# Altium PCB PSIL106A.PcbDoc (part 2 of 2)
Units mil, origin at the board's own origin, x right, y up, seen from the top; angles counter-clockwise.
Board outline 4000 x 3327 mil, 2 copper layers (Top Layer, Bottom Layer), stack 62 mil thick; 63 components, 23 nets, 108 pads, 247 vias.
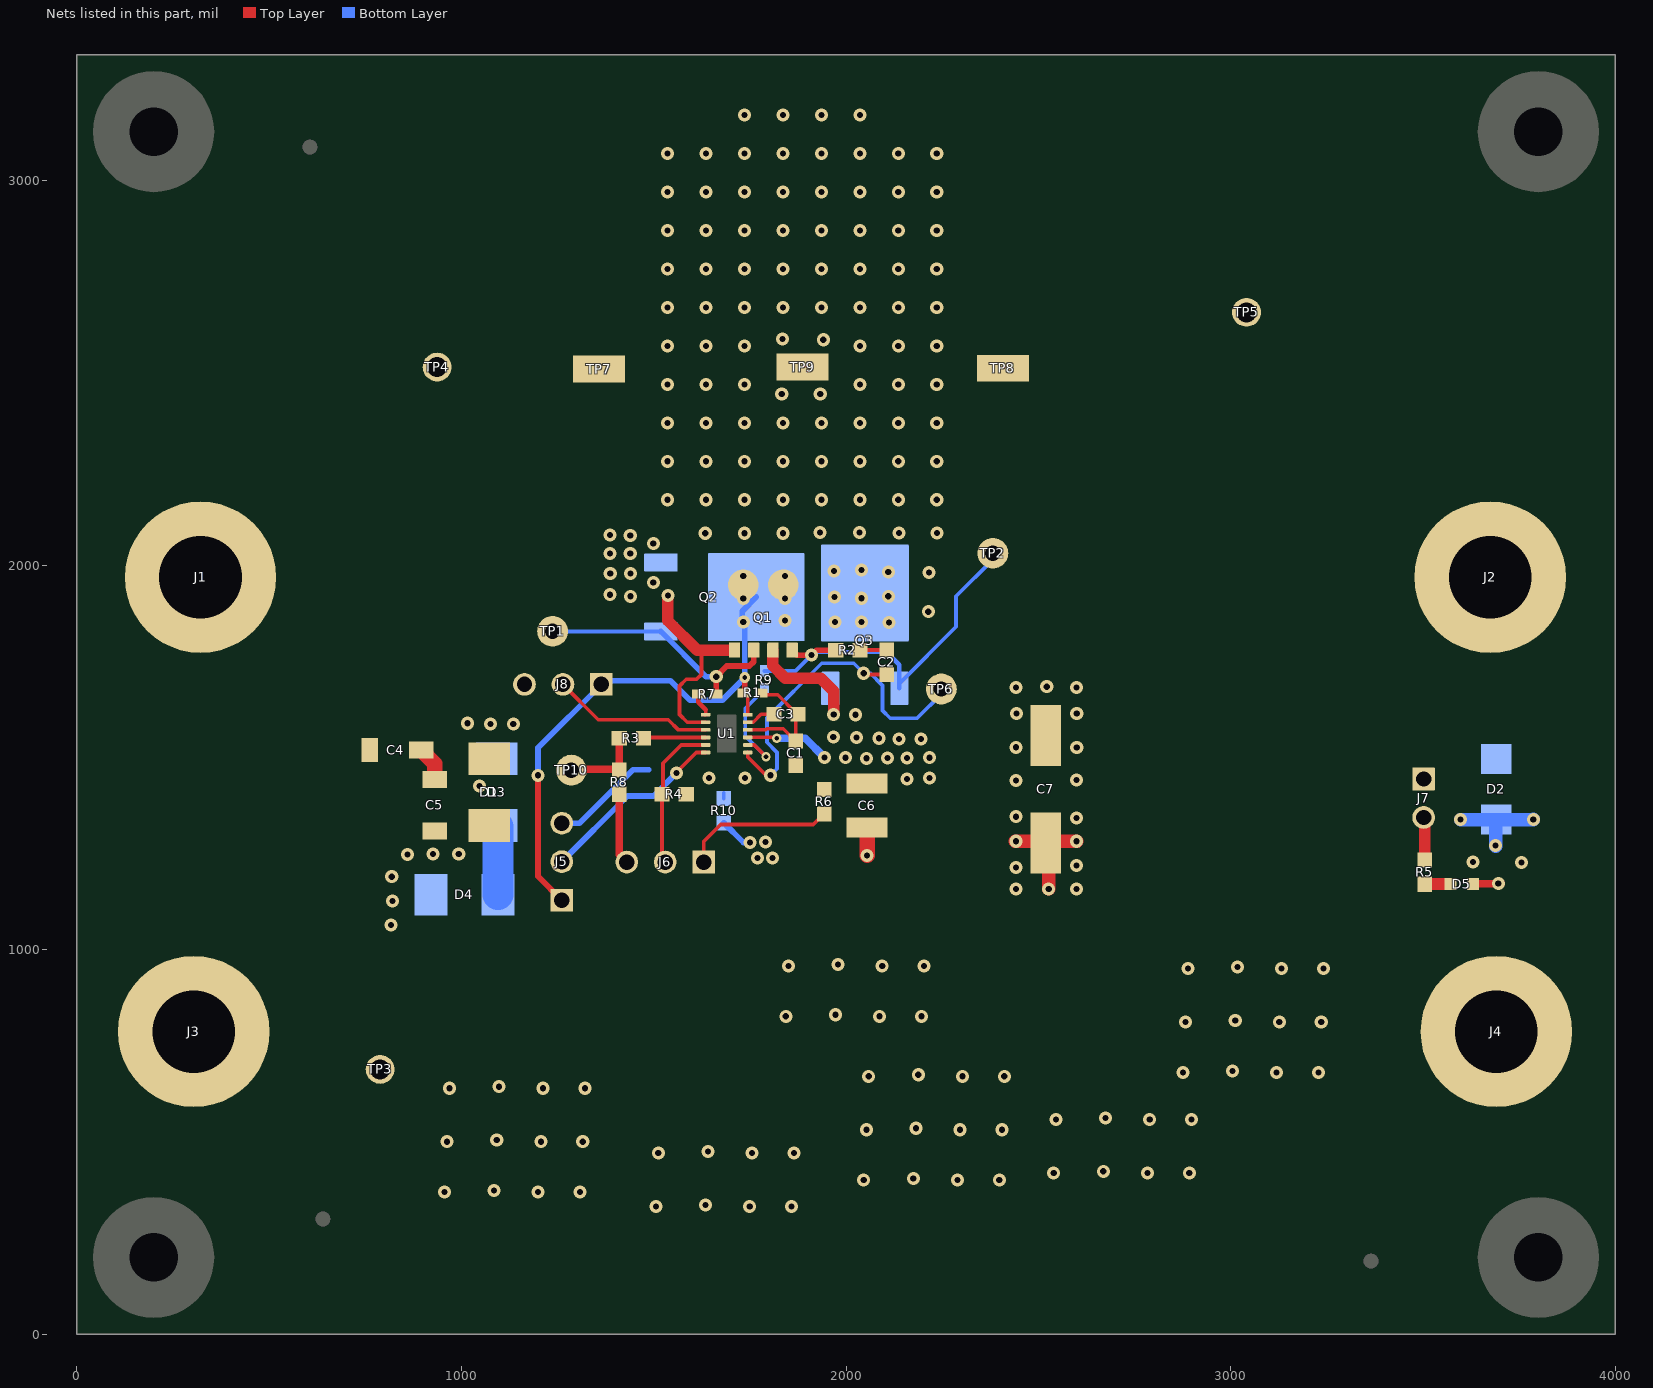
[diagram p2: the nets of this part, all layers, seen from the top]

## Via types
v1: diameter 34, hole 16, Top Layer to Bottom Layer, 241 vias
v2: diameter 19.68, hole 7.87, Top Layer to Bottom Layer, 3 vias
v3: diameter 24, hole 12, Top Layer to Bottom Layer, 2 vias
v4: diameter 28, hole 12, Top Layer to Bottom Layer, 1 vias

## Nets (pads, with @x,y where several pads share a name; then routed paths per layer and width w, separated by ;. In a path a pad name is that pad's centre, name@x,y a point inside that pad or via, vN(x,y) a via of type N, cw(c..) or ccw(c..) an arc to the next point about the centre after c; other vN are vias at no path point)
AGND: C1.2 C2.2 J5.3 R4.1 R10.2 TP6.1 U1.7 | length 1266.5
  Top Layer w10: U1.7@1744.49,1512.8 1744.49,1501.03 1791.77,1453.75 v1(1804,1453.75) ; v1(2046,1719) 2048.88,1716.12 C2.2@2106,1716.12
  Bottom Layer w10: R10.2@1682,1393.28 R10.2@1682,1408.17 ; v1(1804,1453.75) 1821,1470.75 1821,1513.33 1794.61,1539.72 1794.61,1602.76 1936.85,1745 2020,1745 v1(2046,1719) 2063.46,1719 2095,1687.46 2095,1621.9 2114.9,1602 2185,1602 2248,1665 TP6.1@2248,1678
  Bottom Layer w15: J5.3@1261,1329 1307,1329 1446,1468 1487,1468
  other v1: 1644,1446.17 1737,1447
NetC1_1: C1.1 C3.2 R1.1 U1.10 | length 312.7
  Top Layer w9.6: U1.10@1744.49,1571.85 1791,1571.85 1793.95,1574.8 1836.7,1574.8 C1.1@1869,1542.5 1869,1605.5 C3.2@1874.5,1611 ; R1.1@1794.62,1663 1822.5,1663 1868.99,1616.5 C3.2@1874.5,1611 ; C3.2@1875.5,1612 C3.2@1874.5,1611
NetC2_1: C2.1 R2.1 | length 69.6
  Top Layer w10: R2.1@2036.5,1778.96 2105.85,1778.96 C2.1@2106,1779.12
NetC3_1: C3.1 U1.11 | length 79.3
  Top Layer w9.5: U1.11@1744.49,1591.54 1758.81,1591.54 1779.27,1612 C3.1@1812.5,1612 ; C3.1@1815.5,1605 C3.1@1817.5,1607
NetC4_1: C4.1 D1.2 D3.1 J1.1 J8.3 Q1.1 Q2.3 TP7.1 U1.2 | length 557.9
  Top Layer w9.7: 1613.04,1778.96 1624,1768 1624,1716 1611.63,1703.63 1584.63,1703.63 1567,1686 1567,1612 1587.46,1591.54 U1.2@1635.04,1591.54
  Top Layer w30: v1(1537,1921) 1537,1855 1613.04,1778.96 Q1.1@1710,1778.96
  other v1: 1047.31,1426 1076,1587 1135,1587 1016,1589 1439.25,1919 1386,1923.24 1499,1955 1387,1978 1439.25,1978 1386,2030 1439,2030 1499,2056 1439,2077 1386,2078
NetC4_2: C4.2 C5.1 | length 90.9
  Top Layer w40: C4.2@895.63,1519.29 930.64,1484.28 C5.1@930.64,1442.86
NetC6_1: C6.1 C7.1 D2.1 J2.1 J7.1 Q1.3 Q3.3 R6.2 TP8.1 U1.9 | length 507.9
  Top Layer w9.6: U1.9@1744.65,1552 U1.9@1744.49,1552.17 1817.83,1552.17 v3(1820,1550)
  Top Layer w30: Q1.3@1810,1778.96 1810,1738 1842,1706 1934.36,1706 1968,1672.36 v1(1968,1612)
  Bottom Layer w20: v3(1820,1550) 1894.06,1550 v1(1944.06,1500)
  other v1: 2442,1440 2599,1441 2159,1444 2217,1446.46 2053,1497.79 2108,1498.3 1999,1499.37 2159,1498.76 2217,1499.37 2442,1526.4 2600,1526 2138,1548 2195,1548 2086,1550 2027,1552 1967,1553 2025,1611 2443.34,1614 2600,1614 2442,1682 2599.66,1682.31 2522,1684
NetD3_2: D3.2 D4.2 | length 184.5
  Bottom Layer w20: D4.2@1092.51,1145.49 D4.2@1095.01,1143
  Bottom Layer w30: D3.2@1092.51,1322.98 D3.2@1095.01,1320.49
  Bottom Layer w80: D4.2@1095.01,1143 D3.2@1095.01,1320.49
NetD5_1: D5.1 R5.1 | length 66.7
  Top Layer w30: R5.1@3505,1170.5 3505.5,1171 D5.1@3571.47,1171
NetJ5_1: J5.1 J8.1 Q1.5-6 Q1.7-8 Q2.4 Q3.4 R1.2 TP9.1 U1.12 | length 1402.1
  Top Layer w10: R1.2@1737,1674 1744.49,1666.51 U1.12@1744.49,1611.22
  Top Layer w15: v1(1199,1453.6) 1199,1191 J5.1@1261,1129 ; R1.2@1737,1674 v4(1737,1708)
  Bottom Layer w15: v1(1199,1453.6) 1199,1525 J8.1@1364,1690 1373.18,1699.18 1543.39,1699.18 1594.09,1648.47 1678.47,1648.47 1737,1707 v4(1737,1708) Q2.4@1737,1845 ; Q2.4@1730,1845 1730,1880.32 Q2.4@1766.68,1917
  other v1: 2112,1851 1733,1852 1971,1852 2040,1852 1841,1856 2214,1879 1733,1913 1841,1913 2040,1914 1970,1917 2110,1919 1733,1972 1841,1972 2216,1981 2110,1982 1969,1985 2040,1987 1634,2083 1736,2083 1836,2083 2138,2083.45 2237,2083.45 1932,2085 2035,2085 1536,2170 1636,2170 1736,2170 1836,2170 1936,2170 2036,2170 2136,2170 2236,2170 1536,2270 1636,2270 1736,2270 1836,2270 1936,2270 2036,2270 2136,2270 2236,2270 1536,2370 1636,2370 1736,2370 1836,2370 1936,2370 2036,2370 2136,2370 2236,2370 1833,2445 1933,2445 1536,2470 1636,2470 1736,2470 2036,2470 2136,2470 2236,2470 1536,2570 1636,2570 1736,2570 2036,2570 2136,2570 2236,2570 1941,2586 1835,2588 1536,2670 1636,2670 1736,2670 1836,2670 1936,2670 2036,2670 2136,2670 2236,2670 1536,2770 1636,2770 1736,2770 1836,2770 1936,2770 2036,2770 2136,2770 2236,2770 1536,2870 1636,2870 1736,2870 1836,2870 1936,2870 2036,2870 2136,2870 2236,2870 1536,2970 1636,2970 1736,2970 1836,2970 1936,2970 2036,2970 2136,2970 2236,2970 1536,3070 1636,3070 1736,3070 1836,3070 1936,3070 2036,3070 2136,3070 2236,3070 1736,3170 1836,3170 1936,3170 2036,3170
NetJ5_2: J5.2 U1.6 | length 490.9
  Top Layer w9.8: v1@1559.66,1461.66 1610.8,1512.8 U1.6@1635.04,1512.8
  Bottom Layer w15: J5.2@1261,1229 1432,1400 1499.66,1400 v1(1559.66,1460)
NetJ6_1: J6.1 R6.1 | length 396.1
  Top Layer w10: J6.1@1630,1228 1630,1281.08 1674.3,1325.38 1914.93,1325.38 R6.1@1943,1353.44
NetJ6_2: J6.2 R4.2 U1.5 | length 392.3
  Top Layer w9.8: J6.2@1530,1228 1521.5,1236.5 R4.2@1521.5,1404 1524,1406.5 1524,1485 1571.48,1532.48 U1.5@1635.04,1532.48
NetJ6_3: J6.3 R8.2 | length 184.3
  Top Layer w20: R8.2@1410.5,1404.18 1410.5,1247.5 J6.3@1430,1228
NetJ7_2: J7.2 R5.2 | length 111.7
  Top Layer w30: J7.2@3502,1344 3505,1341 R5.2@3505,1233.5
NetJ8_2: J8.2 U1.3 | length 420
  Top Layer w9.8: 1564.15,1571.85 U1.3@1635.04,1571.85
  Top Layer w10: J8.2@1264,1690 1356,1598 1538,1598 1564.15,1571.85
NetQ1_2: Q1.2 Q2.1 R7.2 TP1.1 | length 668
  Top Layer w15: R7.2@1662.62,1665 v1(1662.62,1710) 1690.12,1737.5 1748.5,1737.5 1760,1749 Q1.2@1760,1778.96
  Bottom Layer w10: TP1.1@1238,1812 1253.24,1827.24 Q2.1@1518.65,1827.24
  Bottom Layer w15: Q2.1@1518.65,1827.24 1635.88,1710 v1(1662.62,1710)
NetQ1_4: Q1.4 Q3.1 R2.2 R9.2 TP2.1 | length 1009.6
  Top Layer w15: Q1.4@1860,1778.96 1872.96,1766 v1(1910,1766) 1922.96,1778.96 R2.2@1973.5,1778.96
  Bottom Layer w10: R9.2@1787.99,1724.62 1868.62,1724.62 v1(1910,1766) 1918,1774 2105.9,1774 2106.9,1773 ; Q3.1@2138.76,1692.76 2286,1840 2286,1919 2382,2015 TP2.1@2382,2031
  Bottom Layer w12: 2106.9,1773 2138.76,1741.14 2138.76,1692.76 Q3.1@2138.76,1679.65
NetR3_1: R3.1 R8.1 TP10.1 | length 176.3
  Top Layer w20: TP10.1@1302.53,1469 1408.68,1469 R8.1@1410.5,1467.17 R3.1@1410.5,1534.71
NetR3_2: R3.2 U1.4 | length 144.1
  Top Layer w9.8: R3.2@1490.95,1552.17 U1.4@1635.04,1552.17
NetR7_1: R7.1 U1.1 | length 65.2
  Top Layer w9: U1.1@1635.04,1611.22 1635.04,1623.96
  Top Layer w10: U1.1@1631.81,1611.22 U1.1@1635.04,1611.22
  Top Layer w12: R7.1@1615.38,1665 1615.38,1643.62 1635.04,1623.96
NetR9_1: R9.1 U1.8 | length 278.6
  Top Layer w9.7: U1.8@1744.49,1532.48 1761.52,1532.48 v3(1792,1502)
  Bottom Layer w9.7: R9.1@1787.99,1677.38 1738,1627.39 1738,1556 v3(1792,1502)
SGND: C5.2 C6.2 C7.2 D1.1 D2.2 D4.1 D5.2 J3.1 J4.1 R10.1 TP3.1 TP4.1 TP5.1 | length 795
  Top Layer w20: D1.1@1090,1320.46 D1.1@1092.52,1322.98 ; D5.2@3630.53,1171 3631.53,1172 v1(3696,1172) 3703,1172 v1@3702,1171
  Top Layer w30: D1.1@1092.52,1322.98 1095.61,1319.89 D1.1@1096.21,1319.89
  Top Layer w35: v1@2439.71,1282.23 v1(2442,1282.23) 2515.01,1282.23 C7.2@2519.68,1277.56 ; v1(2527,1158) 2527,1267.24 2524,1270.24 2525.5,1271.74 C7.2@2519.68,1277.56 ; v1(2599.66,1282.23) 2524.36,1282.23 C7.2@2519.68,1277.56
  Top Layer w40: v1(2055,1245) C6.2@2055,1317.91
  Bottom Layer w15: R10.1@1682,1330.28 1733.28,1279 v1(1750.28,1279)
  Bottom Layer w35: v1(3598.06,1338.58) D2.2@3690.94,1338.58 ; v1@3689,1269 v1(3689,1270.88) 3689,1330.53 3694,1335.53 D2.2@3690.94,1338.58 ; v1(3787,1339) 3786.58,1338.58 D2.2@3690.94,1338.58
  other v1: 1506,332.38 1749.62,332.38 1858.62,332.38 1635,336.38 956,370 1199.62,370 1308.62,370 1085,374 2046,401 2289.62,401 2398.62,401 2175,405 2540,420 2783.62,420 2892.62,420 2669,424 1512,471.38 1755.62,471.38 1864.62,471.38 1641,475.38 963,501 1206.62,501 1315.62,501 1092,505 2053,532 2296.62,532 2405.62,532 2182,536 2546,559 2789.62,559 2898.62,559 2675,563 969,640 1212.62,640 1321.62,640 1098,644 2059,671 2302.62,671 2411.62,671 2188,675 2876,681 3119.62,681 3228.62,681 3005,685 2883,812 3126.62,812 3235.62,812 3012,816 1843.5,827 2087.13,827 2196.13,827 1972.5,831 2889,951 3132.62,951 3241.62,951 3018,955 1850.5,958 2094.13,958 2203.13,958 1979.5,962 817,1064.5 820.46,1126.97 2442,1158 2599.66,1158 818.89,1190 2442,1214.23 2599.66,1218.73 3756.04,1227 3630.53,1228 1770,1238.36 1809,1239 860,1248 926,1249 993.24,1249 1791,1280 2599.66,1343 2442,1346
pads on no net: FID1.1 FID2.1 FID3.1 FID4.1 FID5.1 FID6.1 H1.1 H2.1 H3.1 H4.1 H5.0 H6.0 H7.0 H8.0 U1.13
copper on no net:
  other v2: 1689.76,1522.64 1690.76,1562.01 1689.76,1601.38

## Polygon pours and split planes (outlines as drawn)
NetC4_1 on Top Layer "TOP_LAYER_NETC4_1_P023" (solid, remove dead copper, pour order 23): 1603.25,2008.95 1616,1996.2 1616,1834.51 1649.51,1801 1726,1801 1732.6,1794.4 1732.6,1759.6 1702,1729 1571.51,1729 1541,1698.49 1541,1638 1426.26,1638 1294.52,1638 1189,1532.48 1189.7,1531.78 1190,1466.17 1190,1400 101.02,1400 39.37,1461.67 39.37,2116.14 39.37,2999.37 293,3253 1446.41,3253 1461.41,3238 1461.41,2150.79
SGND on Top Layer "TOP_LAYER_SGND_P021" (solid, remove dead copper, pour order 21): 3949,1369 3982,1336 3982,37 2167,37 262,37 38,261 38,1369
AGND on Top Layer "TOP_LAYER_AGND_P007" (solid, remove dead copper, pour order 7): 1575,1514.32 1855,1514.32 1888,1514.32 1888,1373.02 1679.03,1373.02 1575,1373.02
NetJ5_1 on Top Layer "TOP_LAYER_NETJ5_1_P009" (solid, remove dead copper, pour order 9): 1602.99,2044.57 1644,2003.56 1644,1859.92 1675.75,1828.17 1899.83,1828.17 2263,1828.17 2263,3254 2260,3257 1510,3257 1501,3248 1501,2146 1592.5,2054.5 1602.43,2044.57
NetC6_1 on Top Layer "TOP_LAYER_NETC6_1_P010" (solid, remove dead copper, pour order 10): 1918.34,1405.66 1913,1411 1913,1526 1932,1545 1932,1642 1882,1692 1833,1692 1792.87,1732.13 1792.87,1798 1878,1798 2081.99,1594.01 2312.01,1594.01 2312.01,3225.01 2345,3258 3765,3258 3954,3069 3954,1448 3912.04,1406.04 2841,1406 2841.5,1405.66
SGND on Bottom Layer "BOTTOM_LAYER_SGND_P017" (solid, remove dead copper, pour order 17): 31,3291 3962,3291 3962,40 31,40
NetJ5_1 on Bottom Layer "BOTTOM_LAYER_NETJ5_1_P011" (solid, remove dead copper, pour order 11): 1635.04,2013 1500,2148.04 1500,3262 1521,3283 2233,3283 2262,3254 2262,1838 2226,1802 1635.04,1802
NetC6_1 on Bottom Layer "BOTTOM_LAYER_NETC6_1_P008" (solid, remove dead copper, pour order 8): 1848.73,1730.75 2677,1730.75 2677,1389 1848.73,1389
AGND on Bottom Layer "BOTTOM_LAYER_AGND_P003" (solid, remove dead copper, pour order 3): 1794.25,1592.25 1831.4,1555.09 1833,1504 1833,1390 1832.51,1389.51 1832.51,1373 1713.46,1373 1679.05,1373 1677.09,1374.96 1460,1374.96 1460,1592.25
NetC6_1 on Bottom Layer "BOTTOM_LAYER_NETC6_1_P014" (solid, remove dead copper, pour order 14): 3619,1480 3646,1453 3741,1453 3764,1476 3764,1747 3886,1869 3886,2054.96 3763.96,2177 3583,2177 3467,2061 3467,1886 3619,1734
NetC4_1 on Bottom Layer "BOTTOM_LAYER_NETC4_1_P002" (solid, remove dead copper, pour order 2): 1549,1886 1310,1886 1277,1919 1277,2127 1301,2151 1461.2,2151 1561,2051.2 1561,1898
NetC4_1 on Bottom Layer "BOTTOM_LAYER_NETC4_1_P025" (solid, remove dead copper, pour order 25): 966,1625 966,1404 1181.1,1404 1181.1,1624.9 1181,1625

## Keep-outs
Keep-Out Layer:
  text ".Layer_Name" at 577,-858.49 h60

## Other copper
Top Layer:
  pour cut-out: 1411,1646.61 1411,1731.89 1402.89,1740 1236.61,1740 1228,1731.39 1228,1680 1262,1646 1262,1584 1372,1584 1411,1623
  pour cut-out: 1680,1272 1680,1189.61 1668.39,1178 1404,1178 1385.29,1196.71 1385.29,1244 1403.29,1262 1651.76,1262 1661.76,1272
  pour cut-out: 1375.2,1359.5 1311,1359.5 1311,1383 1371.2,1383 1375.2,1383
  pour cut-out: 1307,1081 1311,1085 1311,1369 1305.94,1369 1305.94,1098.94 1298,1091 1226,1091 1223,1094 1223,1136 1221,1138 1216.76,1138 1215.76,1137 1215.76,1084.24 1219,1081
  text ".Layer_Name" at 577,-858.49 h60
Bottom Layer:
  pour cut-out: 3593.51,1546 3593.51,1452.49 3620,1426 3760,1426 3789.49,1455.49 3789.49,1540 3778,1540 3778,1513 3777,1512 3777,1462 3750,1435 3630,1435 3604,1461 3604,1546
  pour cut-out: 3462.18,1490 3537.71,1490 3550,1477.71 3550,1323 3521,1294 3482,1294 3452,1324 3452,1479.82
  text ".Layer_Name" at 577,-858.49 h60

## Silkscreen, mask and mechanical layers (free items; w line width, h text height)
Top Overlay:
  lines w6: 1568,1963 1568,2034
  text "'.PRJ_Number'.PCB_Rev" at 2397,2832 h150
  text "LM74800EVM-CD" at 327,2822 h150
  text "VOUT" at 2340,2640 h35
  text "GND4" at 3123,2638 h35
  text "GND3" at 882,2634 h35
  text "VIN" at 1309,2634 h35
  text "VOUT_ALWAYS_ON" at 1752.36,2599 h35
  text "VOUT+" at 3532,2278 h60
  text "HGATE" at 2457,2007.7 h35
  text "DGATE" at 984.25,1807.5 h35
  text "GND2" at 2203.13,1782.58 h30
  text "VIN+" at 224,1666 h60
  text "VIN_MON" at 1162.51,1569.58 h30
  text "VIN-" at 208,1038 h60
  text "GND1" at 728.77,802 h35
  text "VOUT-" at 3568,480 h60
  text ".Layer_Name" at 577,-858.49 h60
Bottom Overlay:
  circle w10: c2138.9,1603.76 r15
  circle w10: c1513.54,1767 r15
  text ".Layer_Name" at 577,-858.49 h60
Top Paste:
  text ".Layer_Name" at 577,-858.49 h60
Bottom Paste:
  text ".Layer_Name" at 577,-858.49 h60
Top Solder:
  text ".Layer_Name" at 577,-858.49 h60
  text ".Layer_Name" at 577,-858.49 h60
Bottom Solder:
  text ".Layer_Name" at 577,-858.49 h60
Drill Guide:
  text ".Layer_Name" at 577,-858.49 h60
M1 Board Outline:
  the board outline again, w10
  text ".Layer_Name" at 962.71,-858.49 h60
M2 Board Dimensions:
  rectangle: 0,-275 125,-150
  rectangle: 125,-400 500,-275
  lines w7: 0,-275 1000,-275 ; 125,-400 125,-150 ; 250,-400 250,-150 ; 500,-400 500,-150 ; 750,-400 750,-150 ; 0,-400 1000,-400 1000,-150 0,-150 0,-400
M3 3D STEP Top:
  text ".Layer_Name" at 577,-858.49 h60
M4 3D STEP Bottom:
  text ".Layer_Name" at 577,-858.49 h60
M5 Assembly Top:
  lines w10: -292,-930.17 6308,-930.17 ; -292,-726.83 6310,-726.83 ; -292,-523.5 -292,-1133.5 3713,-1133.5 6310,-1133.5 6310,-523.5 -291.5,-523.5 -291.5,-1133.5 1284,-1133.5 ; 2173,-1133.5 2173,-523.5 ; 3440,-726.83 3440,-523.5 ; 4280,-726.83 4280,-523.5 ; 4902,-1140 4902,-937.17
  text "COMPONENTS MARKED 'DNP' SHOULD NOT BE POPULATED." at 1153.5,-318.5 h60
  text "ASSEMBLY VARIANT:" at 1153,-434 h60
  text ".VariantName" at 2189,-434 h60
  text "PCB VIEWED FROM TOP SIDE" at -228.5,-655.67 h60
  text "BOARD #:" at 2248,-655.67 h60
  text ".PRJ_Number" at 2793.5,-655.67 h60
  text "REV:" at 3638,-655.67 h60
  text ".PCB_Rev" at 3929.5,-655.67 h60
  text "SVN REV:" at 4476,-655.67 h60
  text ".VersionControl_RevNumber" at 4982,-655.67 h60
  text "TID #:" at 2248,-859 h60
  text ".TID" at 2793.5,-859 h60
  text "LAYER NAME=" at -141,-863 h60
  text ".LAYER_NAME" at 680,-863 h60
  text "PLOT NAME =" at -228.5,-1064.34 h60
  text ".plot_File_Name" at 577,-1064.34 h60
  text "GENERATED    :" at 2250,-1064.34 h60
  text ".Print_Date" at 3119.5,-1064.34 h60
  text ".Print_Time" at 3848.5,-1064.34 h60
  text "TEXAS INSTRUMENTS" at 5113,-1064.34 h60
M6 Assembly Bottom:
  lines w10: -292.5,-727.33 6309.5,-727.33 ; -290.5,-930.67 6309.5,-930.67 ; 1115.5,-1140.5 1115.5,-937.67 ; 1737.5,-727.33 1737.5,-524 ; 2577.5,-727.33 2577.5,-524 ; 3844.5,-1134 3844.5,-524 ; 4733.5,-1134 6309,-1134 6309,-524 -292.5,-524 -292.5,-1134 2304.5,-1134 6309.5,-1134 6309.5,-524
  text "COMPONENTS MARKED 'DNP' SHOULD NOT BE POPULATED." at 6102,-318 h60
  text ".VariantName" at 5058,-434 h60
  text "ASSEMBLY VARIANT:" at 6097,-434 h60
  text ".VersionControl_RevNumber" at 1035.5,-656.17 h60
  text "SVN REV:" at 1541.5,-656.17 h60
  text ".PCB_Rev" at 2088,-656.17 h60
  text "REV:" at 2379.5,-656.17 h60
  text ".PRJ_Number" at 3224,-656.17 h60
  text "BOARD #:" at 3769.5,-656.17 h60
  text "PCB VIEWED FROM BOTTOM SIDE" at 6246,-656.17 h60
  text ".Layer_Name" at 5291,-852 h60
  text "LAYER NAME=" at 6087,-852 h60
  text ".TID" at 3224,-859.5 h60
  text "TID #:" at 3769.5,-859.5 h60
  text "TEXAS INSTRUMENTS" at 904.5,-1064.84 h60
  text ".Print_Time" at 2169,-1064.84 h60
  text ".Print_Date" at 2898,-1064.84 h60
  text "GENERATED    :" at 3767.5,-1064.84 h60
  text ".plot_File_Name" at 5440.5,-1064.84 h60
  text "PLOT NAME =" at 6246,-1064.84 h60
M7 LPKF Text Top:
  text ".Layer_Name" at 774,-856 h60
M8 LPKF Text Bottom:
  text ".Layer_Name" at 785,-835 h60
M9 Title Sheet:
  drawing of 57 lines, arcs and shapes, not listed
  text "1" at 739.84,8036.5 h70
  text "2" at 3235.5,8036.5 h70
  text "3" at 5724.84,8036.5 h70
  text "4" at 8231.51,8036.5 h70
  text "5" at 10730.5,8036.5 h70
  text "6" at 13235.5,8036.5 h70
  text "A" at -416.5,6893.5 h70
  text "A" at 14383.5,6893.5 h70
  text "B" at -416.5,4513.5 h70
  text "B" at 14383.5,4513.5 h70
  text "C" at -416.5,2138.5 h70
  text "C" at 14383.5,2138.5 h70
  text "PROJECT TITLE:" at 11343.5,277.5 h45
  text ".PRJ_Title" at 11393.5,144.17 h70
  text "DESIGNED FOR:" at 11343.5,-23.5 h45
  text ".PRJ_Customer" at 11393.5,-163.5 h70
  text "D" at -416.5,-231.5 h70
  text "D" at 14383.5,-231.5 h70
  text "FILE NAME:" at 11343.5,-323.5 h45
  text ".PCB_File_Name_No_Path" at 11393.5,-443.5 h70
  text "Texas Instruments (TI) and/or its licensors do not warrant the accuracy or completeness of this specification" at 6374,-605.34 h45
  text "ENGINEER:" at 11343.5,-613.5 h45
  text "LAYOUT BY:" at 12848.5,-613.5 h45
  text "or any information contained therein. TI and/or its licensors do not warrant that this design will meet" at 6329.01,-718 h45
  text ".PRJ_Engineer" at 11393.5,-768.49 h70
  text ".PCB_Layout" at 12899,-768.49 h70
  text "the specifications, will be suitable for your application or fit for any particular purpose, or will operate in" at 6329.01,-830.67 h45
  text "ALTIUM DESIGNER VERSION:" at 12848.5,-923.5 h45
  text "an implementation. TI and/or its licensors do not warrant that the design is production worthy. You should" at 6329.01,-943.33 h45
  text "completely validate and test your design implementation to confirm the system functionality for your application." at 6374,-1056 h45
  text ".print_Scale" at 11393.5,-1056.83 h70
  text ".Application_BuildNumber" at 12899,-1056.83 h70
  text "1" at 739.84,-1263.5 h70
  text "2" at 3235.5,-1263.5 h70
  text "3" at 5724.84,-1263.5 h70
  text "4" at 8231.51,-1263.5 h70
  text "5" at 10730.5,-1263.5 h70
  text "6" at 13235.5,-1263.5 h70
M10 Fab Notes:
  drawing of 189 lines, arcs and shapes, not listed
  text "DESIGN INFORMATION" at 12382.02,6356.17 h60
  text "MIN. TRACK WIDTH:" at 11737.46,6224.05 h60
  text "MIL" at 12988.46,6224.05 h60
  text "9" at 12782,6219 h60
  text "MIN. CLEARANCE:" at 11737.46,6099.92 h60
  text "MIL" at 12988.46,6099.92 h60
  text "8" at 12818,6091 h60
  text "NOTE:-" at 4862.5,5985.78 h50
  text "19.685" at 12642,5977 h60
  text "MIN. VIA PAD SIZE:" at 11737.46,5975.8 h60
  text "MIL" at 12988.46,5975.8 h60
  text "0.05mm (2MIL)" at 12432.46,5845.9 h60
  text "1)THIS IS NOT AN IMPEDANCE CONTROLLED BOARD" at 4850.91,5843.7 h50
  text "MINIMUM ANNULAR RING" at 11408.23,5837.67 h60
  text "EXTERNAL" at 13140.46,5837.67 h60
  text "2)ALL VIAS ARE NON TENTED" at 4850.91,5734.12 h50
  text "PER" at 11608.23,5727.55 h60
  text "IPC-D-275 CLASS 2 LEVEL C" at 11828.23,5727.54 h60
  text "MIL, HOLES" at 13316.46,5627.07 h60
  text "+/-" at 12924,5618.48 h60
  text "+/-" at 13778,5618.48 h60
  text "REGISTRATION TOLERANCES:" at 11408.23,5617.42 h60
  text "METAL" at 12608,5617.42 h60
  text "5" at 13184.2,5617.42 h60
  text "3" at 14017.2,5617.42 h60
  text "MIL" at 14133.46,5617.42 h60
  text "3)VENDOR MAY ADJUST SOLDERMASK WHEREVER SOLDERMASK PADS ARE SAME SIZE(1:1)" at 4847.13,5603.53 h50
  text "HOLE SIZE TOLERANCE (UNLESS OTHERWISE SPECIFIED):" at 11408.23,5519.1 h60
  text "+/-" at 13778,5516.23 h60
  text "3" at 14017.2,5515.17 h60
  text "MIL" at 14133.46,5515.17 h60
  text "AS PER MANUFACTURING CAPABILITIES AND ALL OTHER SOLDERMASK PADS SHALL NOT BE MODIFIED" at 4935.13,5490.53 h50
  text "PROVIDED NO ADJACENT COPPER IS EXPOSED AND NO CONFLICT PRODUCED WITH ANY STATED" at 4935.13,5389.53 h50
  text "MATERIAL:" at 11333.46,5377.52 h60
  text "\"VIA TENTING/COVERING\" REQUIREMENTS." at 4935.13,5296.53 h50
  text "FR-4 High Tg" at 12319.9,5249 h60
  text "X" at 12175.46,5241.01 h60
  text "FR-408" at 11754.46,5236.49 h60
  text "OTHER" at 13242.46,5236.49 h60
  text "62 MIL (1.6mm) +/-10%" at 12074.56,5093.46 h60
  text "X" at 11954.46,5091.01 h60
  text "THICKNESS:" at 11408.23,5085.24 h60
  text "OTHER" at 13359.46,5085.24 h60
  text "TOLERANCE:" at 11408.23,4946.92 h60
  text "X" at 12256.46,4946.92 h60
  text "ANSI IPC-6012 TYPE 3 CLASS 2" at 12434.48,4946.92 h60
  text "OTHER +/-" at 12434.46,4802.73 h60
  text "BOW & TWIST:" at 11408.23,4657.54 h60
  text "X" at 12256.46,4657.54 h60
  text "ANSI IPC-6012 TYPE 3 CLASS 2" at 12434.48,4657.54 h60
  text "OTHER +/-" at 12434.46,4510.85 h60
  text "DRILLING:" at 11333.46,4380.23 h60
  text "NC_DRILL FILES" at 13094.46,4275.04 h60
  text "REFERENCE:" at 11408.23,4271.1 h60
  text "X" at 12065.46,4271.01 h60
  text "AS SHOWN" at 12243.46,4271.1 h60
  text "X" at 12966.46,4271.1 h60
  text "OTHER" at 13392.46,4128.85 h60
  text "PTH COPPER THICKNESS:" at 11407.91,4125.32 h60
  text "X" at 12547.14,4125.32 h60
  text "20-30 um" at 12675.14,4125.32 h60
  text "BOARD FINISH:" at 11333.46,3977.73 h60
  text "SILKSCREEN:" at 11488.68,3867.6 h60
  text "X" at 12446.46,3867.6 h60
  text "TOP" at 12563.46,3867.6 h60
  text "X" at 12956.46,3867.6 h60
  text "BOTTOM" at 13074.46,3867.6 h60
  text "SILKSCREEN COLOR:" at 11488.68,3712.41 h60
  text "X" at 12445.46,3712.41 h60
  text "WHITE" at 12563.46,3712.41 h60
  text "OTHER" at 13074.46,3712.41 h60
  text "X" at 12576.46,3568.96 h60
  text "GREEN" at 12694.46,3568.96 h60
  text "OTHER" at 13312.46,3568.96 h60
  text "SOLDER RESIST COLOR:" at 11488.68,3562.1 h60
  text "X" at 12576.46,3414.71 h60
  text "MATTE" at 12694.46,3414.71 h60
  text "SEMI-GLOSS" at 13312,3414.07 h60
  text "IMMERSION GOLD (ENIG)" at 12394.46,3241.94 h60
  text "ENEPIG" at 13732,3234.72 h60
  text "SURFACE FINISH:" at 11333.46,3233.72 h60
  text "X" at 12216.46,3233.72 h60
  text "IMM. TIN/SILVER OR EQUIV" at 11663,3096.4 h60
  text "OTHER" at 13094.46,3092.47 h60
  text "ARRAY/PANEL:" at 11333.46,2937.09 h60
  text "CUT AND TRIM PER M1 BOARD OUTLINE" at 12394.46,2928.87 h60
  text "N.C. ROUTE" at 12394.46,2792.9 h60
  text "X" at 13082.46,2792.9 h60
  text "V. SCORE" at 13260.46,2792.9 h60
  text "CERTIFICATION:" at 11333.46,2663.77 h60
  text "MATERIALS AND WORKMANSHIP FOR ALL PCBS" at 12058.46,2663.77 h60
  text "TO MEET OR EXCEED THE REQUIREMENTS OF:" at 12058.46,2569.71 h60
  text "X" at 11695.97,2441.08 h60
  text "ANSI IPC-A-600F CLASS ->" at 11823.96,2441.08 h60
  text "X" at 13471.97,2441.08 h60
  text "2" at 13581.96,2441.08 h60
  text "1" at 13266.96,2439.58 h60
  text "3" at 13935.96,2439.58 h60
  text "X" at 12507.97,2293.39 h60
  text "RoHS" at 12635.96,2293.39 h60
  text "OTHER" at 13280.36,2293.39 h60
  text "PER ORDER" at 13677.42,2293.39 h60
  text "ALL BOARDS MUST MEET OR EXCEED UL94-V0 REQUIREMENTS." at 11361,2139.57 h60
  text "PCB MUST BEAR THE UL94V-0 UL REGISTERED MATERIAL ID NUMBER" at 11361,2023.5 h60
  text "ADDITIONAL REQUIREMENTS:" at 11333.46,1854.08 h60
  text "MICROSECTION:" at 11408.23,1746.95 h60
  text "YES" at 12313.96,1746.95 h60
  text "REQUIRED" at 13175.46,1602.62 h60
  text "BARE BOARD ELEC. TEST:" at 11408.23,1599.76 h60
  text "NONE" at 12713.96,1599.76 h60
  text "X" at 13057.46,1599.76 h60
  text "PER ORDER" at 13767.46,1599.76 h60
  text "XX MIL VIAS REQUIRE NON-CONDUCTIVE FILL AND PLANARIZE" at 11576.38,1394.82 h59
  text "XX MIL VIAS REQUIRE CONDUCTIVE FILL AND PLANARIZE" at 11584.38,1290.84 h60
  text "OUTER XX MIL TRACES REQUIRE 50 OHM SINGLE-ENDED IMPEDANCE" at 11571,1127 h58
  text "LAYER 2 & 3 (INNER LAYERS) XX MIL WIDE, XX MIL SPACE / TRACES REQUIRE 100 OHM DIFFERENTIAL IMPEDANCE" at 11575.39,891.74 h60
M11 Gerber Information:
  lines w10: -292,-930.17 6308,-930.17 ; -292,-726.83 6310,-726.83 ; -292,-523.5 -292,-1133.5 3713,-1133.5 6310,-1133.5 6310,-523.5 -291.5,-523.5 -291.5,-1133.5 1284,-1133.5 ; 2173,-1133.5 2173,-523.5 ; 3440,-726.83 3440,-523.5 ; 4280,-726.83 4280,-523.5 ; 4902,-1140 4902,-937.17
  text "ALL ARTWORK VIEWED FROM TOP SIDE" at -228.5,-655.67 h60
  text "BOARD #:" at 2248,-655.67 h60
  text ".PRJ_Number" at 2793.5,-655.67 h60
  text "REV:" at 3638,-655.67 h60
  text ".PCB_Rev" at 3929.5,-655.67 h60
  text "SVN REV:" at 4476,-655.67 h60
  text ".VersionControl_RevNumber" at 4982,-655.67 h60
  text "LAYER NAME =" at -228.5,-858.49 h60
  text "TID #:" at 2248,-859 h60
  text ".TID" at 2793.5,-859 h60
  text "PLOT NAME =" at -228.5,-1064.34 h60
  text ".plot_File_Name" at 577,-1064.34 h60
  text "GENERATED    :" at 2250,-1064.34 h60
  text ".Print_Date" at 3119.5,-1064.34 h60
  text ".Print_Time" at 3848.5,-1064.34 h60
  text "TEXAS INSTRUMENTS" at 5113,-1064.34 h60
M12 Stackup:
  lines w15: 5275.2,4025 5685.11,4025 6614.85,4025 7474.62,4025 8124.46,4025 8694.32,4025 ; 5275.2,4145 5685.11,4145 6614.85,4145 7474.62,4145 8124.46,4145 8694.32,4145 ; 5275.2,4265 5685.11,4265 6614.85,4265 7474.62,4265 8124.46,4265 8694.32,4265 ; 5275.2,4385 5685.11,4385 6614.85,4385 7474.62,4385 8124.46,4385 8694.32,4385 ; 5275.2,4505 5685.11,4505 6614.85,4505 7474.62,4505 8124.46,4505 8694.32,4505 ; 5275.2,4625 5685.11,4625 6614.85,4625 7474.62,4625 8124.46,4625 8694.32,4625 ; 5275.2,4745 8694.32,4745 ; 5685.11,4865 5685.11,3905 ; 6614.85,4865 6614.85,3905 ; 7474.62,4865 7474.62,3905 ; 8124.46,4865 8124.46,3905 ; 5685.11,3905 5275.2,3905 5275.2,4865 8694.32,4865 8694.32,3905 8124.46,3905 ; 5685.11,3905 6614.85,3905 ; 6614.85,3905 7474.62,3905 ; 7474.62,3905 8124.46,3905
  text "Layer" at 5345.2,4775 h60
  text "Name" at 5755.11,4775 h60
  text "Material" at 6684.85,4775 h60
  text "Thickness" at 7544.62,4775 h60
  text "Constant" at 8194.46,4775 h60
  text "Top Overlay" at 5755.11,4655 h60
  text "Top Solder" at 5755.11,4535 h60
  text "Solder Resist" at 6684.85,4535 h60
  text "0.40mil" at 7544.62,4535 h60
  text "3.5" at 8194.46,4535 h60
  text "1" at 5345.2,4415 h60
  text "Top Layer" at 5755.11,4415 h60
  text "1.40mil" at 7544.62,4415 h60
  text "Dielectric1" at 5755.11,4295 h60
  text "FR-4 High Tg" at 6684.85,4295 h60
  text "59.20mil" at 7544.62,4295 h60
  text "4.8" at 8194.46,4295 h60
  text "2" at 5345.2,4175 h60
  text "Bottom Layer" at 5755.11,4175 h60
  text "1.40mil" at 7544.62,4175 h60
  text "Bottom Solder" at 5755.11,4055 h60
  text "Solder Resist" at 6684.85,4055 h60
  text "0.40mil" at 7544.62,4055 h60
  text "3.5" at 8194.46,4055 h60
  text "Bottom Overlay" at 5755.11,3935 h60
M13 Component Bodies Top:
  text ".Layer_Name" at 577,-858.49 h60
M14 Component Bodies Bottom:
  text ".Layer_Name" at 577,-858.49 h60
M15 Courtyards Top:
  text ".Layer_Name" at 577,-858.49 h60
M16 Courtyards Bottom:
  text ".Layer_Name" at 577,-858.49 h60
Drill Drawing:
  circle w10: c5045.62,2539.83 r33.33
  lines w10: 5012.29,2356.5 5078.96,2356.5 5078.96,2423.17 5012.29,2423.17 5012.29,2356.5 ; 5012.29,2673.17 5028.96,2673.17 5045.62,2656.5 5062.29,2673.17 5078.96,2673.17 5062.29,2689.83 5078.96,2706.5 5062.29,2706.5 5045.62,2723.17 5028.96,2706.5 5012.29,2706.5 5028.96,2689.83 5012.29,2673.17 ; 5012.29,2873.17 5078.96,2873.17 5045.62,2806.5 5012.29,2873.17 ; 5012.29,2956.5 5078.96,2956.5 5078.96,3023.17 5012.29,3023.17 5012.29,2956.5 ; 5012.29,3123.17 5028.96,3123.17 5028.96,3106.5 5062.29,3106.5 5062.29,3123.17 5078.96,3123.17 5078.96,3156.5 5062.29,3156.5 5062.29,3173.17 5028.96,3173.17 5028.96,3156.5 5012.29,3156.5 5012.29,3123.17 ; 5012.29,3256.5 5045.62,3273.17 5078.96,3256.5 5062.29,3289.83 5078.96,3323.17 5045.62,3306.5 5012.29,3323.17 5028.96,3289.83 5012.29,3256.5 ; 5025.62,2969.83 5065.62,2969.83 5065.62,3009.83 5025.62,3009.83 5025.62,2969.83
  lines w15: 4952.5,2311.5 10626.96,2311.5 ; 4952.5,3361.5 10626.96,3361.5 ; 5503.38,2161.5 5503.38,3511.5 ; 6103.22,2161.5 6103.22,3511.5 ; 7252.88,2161.5 7252.88,3511.5 ; 7758.76,2161.5 7758.76,3511.5 ; 8492.56,2161.5 8492.56,3511.5 ; 9992.11,2161.5 9992.11,3511.5 ; 4952.5,2161.5 10626.96,2161.5 10626.96,3511.5 4952.5,3511.5 4952.5,2161.5
  text "Symbol" at 5042.5,3406.5 h72
  text "Count" at 5548.38,3406.5 h72
  text "Hole Size" at 6148.22,3406.5 h72
  text "Plated" at 7297.88,3406.5 h72
  text "Hole Type" at 7803.76,3406.5 h72
  text "Drill Layer Pair" at 8537.56,3406.5 h72
  text "Via/Pad" at 10037.11,3406.5 h72
  text "3" at 5548.38,3256.5 h60
  text "7.87mil (0.200mm)" at 6148.22,3256.5 h60
  text "PTH" at 7297.88,3256.5 h60
  text "Round" at 7803.76,3256.5 h60
  text "Top Layer - Bottom Layer" at 8537.56,3256.5 h60
  text "Via" at 10037.11,3256.5 h60
  text "3" at 5548.38,3106.5 h60
  text "12.00mil (0.305mm)" at 6148.22,3106.5 h60
  text "PTH" at 7297.88,3106.5 h60
  text "Round" at 7803.76,3106.5 h60
  text "Top Layer - Bottom Layer" at 8537.56,3106.5 h60
  text "Via" at 10037.11,3106.5 h60
  text "241" at 5548.38,2956.5 h60
  text "16.00mil (0.406mm)" at 6148.22,2956.5 h60
  text "PTH" at 7297.88,2956.5 h60
  text "Round" at 7803.76,2956.5 h60
  text "Top Layer - Bottom Layer" at 8537.56,2956.5 h60
  text "Via" at 10037.11,2956.5 h60
  text "15" at 5548.38,2806.5 h60
  text "40.00mil (1.016mm)" at 6148.22,2806.5 h60
  text "PTH" at 7297.88,2806.5 h60
  text "Round" at 7803.76,2806.5 h60
  text "Top Layer - Bottom Layer" at 8537.56,2806.5 h60
  text "Pad" at 10037.11,2806.5 h60
  text "3" at 5548.38,2656.5 h60
  text "52.00mil (1.321mm)" at 6148.22,2656.5 h60
  text "PTH" at 7297.88,2656.5 h60
  text "Round" at 7803.76,2656.5 h60
  text "Top Layer - Bottom Layer" at 8537.56,2656.5 h60
  text "Pad" at 10037.11,2656.5 h60
  text "4" at 5548.38,2506.5 h60
  text "125.98mil (3.200mm)" at 6148.22,2506.5 h60
  text "PTH" at 7297.88,2506.5 h60
  text "Round" at 7803.76,2506.5 h60
  text "Top Layer - Bottom Layer" at 8537.56,2506.5 h60
  text "Pad" at 10037.11,2506.5 h60
  text "4" at 5548.38,2356.5 h60
  text "214.57mil (5.450mm)" at 6148.22,2356.5 h60
  text "PTH" at 7297.88,2356.5 h60
  text "Round" at 7803.76,2356.5 h60
  text "Top Layer - Bottom Layer" at 8537.56,2356.5 h60
  text "Pad" at 10037.11,2356.5 h60
  text "273 Total" at 5548.38,2206.5 h60
  text "Drill tolerances:" at 5514.95,1747.01 h75
  text "For 7.87 mil drill via +0/-7.87 mil" at 5515.95,1537.01 h60
  text "For 12 mil drill via +0/-12 mil" at 5514.95,1393 h60
  text "For 16 mil drill via +0/-16 mil" at 5508,1277 h60
  text "For PTH +/- 3 MIL" at 5514,1164 h60
  text ".Layer_Name" at 577,-858.49 h60
M17 Embedded Cavity:
  text ".Layer_Name" at 577,-858.49 h60
M18 Embedded Assembly:
  text ".Layer_Name" at 577,-858.49 h60
M19 Embedded Keepout:
  text ".Layer_Name" at 577,-858.49 h60

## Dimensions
0,-400 to 1000,-400 on M2 Board Dimensions
0,0 to 0,3327 on M2 Board Dimensions
0,3327 to 4000,3327 on M2 Board Dimensions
